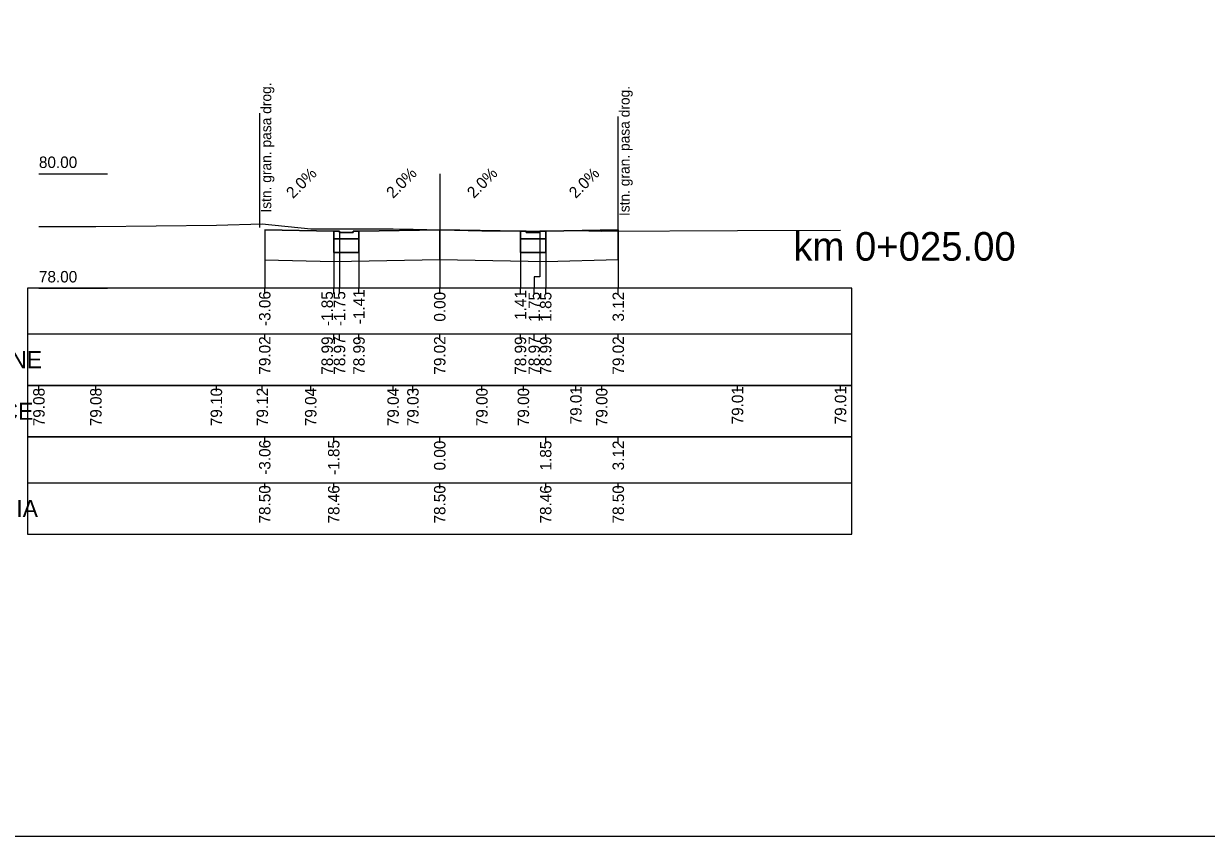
# Model space of a CAD drawing. Extents: x 7492871 to 7493499, y 5802964 to 5802992.
# Drawn here: x 7493052.48 to 7493073.13, y 5802963.88 to 5802978.08 of the extents above; entities that cross this region are included whole.
import ezdxf

# ---------------------------------------------------------------- set-up
doc = ezdxf.new("R2010")
doc.units = 0
for name, color, linetype in [('_wydruk', 7, 'Continuous'), ('opisy_ramki_pop', 7, 'Continuous'), ('pop_comp_kostka', 7, 'Continuous'), ('pop_comp_lawa', 7, 'Continuous'), ('pop_comp_scieralna', 7, 'Continuous'), ('pop_granica_istn', 7, 'Continuous'), ('pop_opis', 7, 'Continuous'), ('pop_os', 7, 'Continuous'), ('pop_pikietaz', 7, 'Continuous'), ('pop_teren', 7, 'Continuous')]:
    doc.layers.add(name, color=color, linetype=linetype)

msp = doc.modelspace()

# ---------------------------------------------------------------- linework, layer by layer
msp.add_lwpolyline([(7493056.687, 5802974.476), (7493057.892, 5802974.452), (7493057.992, 5802974.452), (7493057.993, 5802974.432), (7493058.232, 5802974.432), (7493058.233, 5802974.452), (7493058.333, 5802974.452), (7493059.743, 5802974.48), (7493061.153, 5802974.452), (7493061.253, 5802974.452), (7493061.254, 5802974.432), (7493061.493, 5802974.432), (7493061.494, 5802974.452), (7493061.594, 5802974.452), (7493062.862, 5802974.477)])
at = {"layer": '_wydruk'}
msp.add_lwpolyline([(7492871.369, 5802992.281), (7493499.283, 5802992.281), (7493499.283, 5802963.881), (7492871.369, 5802963.881)], close=True, dxfattribs=at)
at = {"layer": 'opisy_ramki_pop'}
for points in [[(7493056.687, 5802973.956), (7493056.687, 5802973.659), (7493056.687, 5802973.659), (7493056.687, 5802973.459)], [(7493057.892, 5802973.923), (7493057.892, 5802973.659), (7493057.892, 5802973.659), (7493057.892, 5802973.459)], [(7493059.743, 5802973.96), (7493059.743, 5802973.659), (7493059.743, 5802973.659), (7493059.743, 5802973.459)], [(7493061.594, 5802973.923), (7493061.594, 5802973.659), (7493061.594, 5802973.659), (7493061.594, 5802973.459)], [(7493062.862, 5802973.957), (7493062.862, 5802973.659), (7493062.862, 5802973.659), (7493062.862, 5802973.459)]]:
    msp.add_lwpolyline(points, dxfattribs=at)
at = {"layer": 'pop_comp_kostka'}
for p, q in [((7493057.992, 5802974.452), (7493057.892, 5802974.452)), ((7493057.892, 5802974.452), (7493057.892, 5802974.322)), ((7493057.892, 5802974.322), (7493058.333, 5802974.322)), ((7493057.993, 5802974.432), (7493057.992, 5802974.452)), ((7493058.232, 5802974.432), (7493057.993, 5802974.432)), ((7493058.233, 5802974.452), (7493058.232, 5802974.432)), ((7493058.333, 5802974.452), (7493058.233, 5802974.452)), ((7493058.333, 5802974.322), (7493058.333, 5802974.452)), ((7493061.253, 5802974.452), (7493061.153, 5802974.452)), ((7493061.153, 5802974.452), (7493061.153, 5802974.322)), ((7493061.153, 5802974.322), (7493061.594, 5802974.322)), ((7493061.254, 5802974.432), (7493061.253, 5802974.452)), ((7493061.493, 5802974.432), (7493061.254, 5802974.432)), ((7493061.494, 5802974.452), (7493061.493, 5802974.432)), ((7493061.594, 5802974.452), (7493061.494, 5802974.452)), ((7493061.594, 5802974.322), (7493061.594, 5802974.452))]:
    msp.add_line(p, q, dxfattribs=at)
at = {"layer": 'pop_comp_lawa'}
for p, q in [((7493058.333, 5802974.322), (7493057.892, 5802974.322)), ((7493057.892, 5802974.322), (7493057.892, 5802974.081)), ((7493058.333, 5802974.081), (7493058.333, 5802974.322)), ((7493061.594, 5802974.322), (7493061.153, 5802974.322)), ((7493061.153, 5802974.322), (7493061.153, 5802974.081)), ((7493061.594, 5802974.081), (7493061.594, 5802974.322)), ((7493057.892, 5802974.081), (7493058.333, 5802974.081)), ((7493061.153, 5802974.081), (7493061.594, 5802974.081))]:
    msp.add_line(p, q, dxfattribs=at)
at = {"layer": 'pop_comp_scieralna'}
for p, q in [((7493057.892, 5802974.452), (7493056.687, 5802974.476)), ((7493056.687, 5802974.476), (7493056.687, 5802973.956)), ((7493057.892, 5802974.081), (7493057.892, 5802974.452)), ((7493059.743, 5802974.48), (7493058.333, 5802974.452)), ((7493058.333, 5802974.452), (7493058.333, 5802974.081)), ((7493059.743, 5802973.96), (7493059.743, 5802974.48)), ((7493061.153, 5802974.452), (7493059.743, 5802974.48)), ((7493059.743, 5802974.48), (7493059.743, 5802973.96)), ((7493061.153, 5802974.081), (7493061.153, 5802974.452)), ((7493062.862, 5802974.477), (7493061.594, 5802974.452)), ((7493061.594, 5802974.452), (7493061.594, 5802974.081)), ((7493062.862, 5802973.957), (7493062.862, 5802974.477)), ((7493056.687, 5802973.956), (7493057.892, 5802973.923)), ((7493058.333, 5802974.081), (7493057.892, 5802974.081)), ((7493057.892, 5802973.923), (7493059.743, 5802973.96)), ((7493059.743, 5802973.96), (7493061.594, 5802973.923)), ((7493061.594, 5802974.081), (7493061.153, 5802974.081)), ((7493061.594, 5802973.923), (7493062.862, 5802973.957))]:
    msp.add_line(p, q, dxfattribs=at)
at = {"layer": 'pop_granica_istn'}
for p, q in [((7493056.603, 5802975.018), (7493056.603, 5802976.518)), ((7493062.862, 5802974.957), (7493062.862, 5802976.457)), ((7493056.603, 5802974.518), (7493056.603, 5802975.018)), ((7493062.862, 5802974.457), (7493062.862, 5802974.957))]:
    msp.add_line(p, q, dxfattribs=at)
at = {"layer": 'pop_opis'}
for p, q in [((7493052.743, 5802975.459), (7493053.943, 5802975.459)), ((7493052.543, 5802973.459), (7493052.543, 5802971.759)), ((7493052.543, 5802973.459), (7493052.543, 5802971.759)), ((7493052.543, 5802973.459), (7493052.543, 5802971.759)), ((7493052.543, 5802973.459), (7493052.543, 5802971.759)), ((7493052.743, 5802973.459), (7493053.943, 5802973.459)), ((7493056.687, 5802973.359), (7493056.687, 5802973.459)), ((7493057.892, 5802973.359), (7493057.892, 5802973.459)), ((7493057.993, 5802973.359), (7493057.993, 5802973.459)), ((7493058.333, 5802973.359), (7493058.333, 5802973.459)), ((7493059.743, 5802973.359), (7493059.743, 5802973.459)), ((7493061.153, 5802973.359), (7493061.153, 5802973.459)), ((7493061.394, 5802973.359), (7493061.394, 5802973.459)), ((7493061.594, 5802973.359), (7493061.594, 5802973.459)), ((7493062.862, 5802973.359), (7493062.862, 5802973.459)), ((7493052.543, 5802972.659), (7493066.943, 5802972.659)), ((7493052.543, 5802972.659), (7493066.943, 5802972.659)), ((7493052.543, 5802972.659), (7493066.943, 5802972.659)), ((7493052.543, 5802972.659), (7493066.943, 5802972.659)), ((7493056.687, 5802972.559), (7493056.687, 5802972.659)), ((7493057.892, 5802972.559), (7493057.892, 5802972.659)), ((7493057.993, 5802972.559), (7493057.993, 5802972.659)), ((7493058.333, 5802972.559), (7493058.333, 5802972.659)), ((7493059.743, 5802972.559), (7493059.743, 5802972.659)), ((7493061.153, 5802972.559), (7493061.153, 5802972.659)), ((7493061.394, 5802972.559), (7493061.394, 5802972.659)), ((7493061.594, 5802972.559), (7493061.594, 5802972.659)), ((7493062.862, 5802972.559), (7493062.862, 5802972.659)), ((7493052.543, 5802971.759), (7493052.543, 5802970.859)), ((7493052.743, 5802971.659), (7493052.743, 5802971.759)), ((7493053.738, 5802971.659), (7493053.738, 5802971.759)), ((7493055.842, 5802971.659), (7493055.842, 5802971.759)), ((7493056.645, 5802971.659), (7493056.645, 5802971.759)), ((7493057.49, 5802971.659), (7493057.49, 5802971.759)), ((7493058.929, 5802971.659), (7493058.929, 5802971.759)), ((7493059.275, 5802971.659), (7493059.275, 5802971.759)), ((7493060.48, 5802971.659), (7493060.48, 5802971.759)), ((7493061.204, 5802971.659), (7493061.204, 5802971.759)), ((7493062.122, 5802971.659), (7493062.122, 5802971.759)), ((7493062.572, 5802971.659), (7493062.572, 5802971.759)), ((7493064.944, 5802971.659), (7493064.944, 5802971.759)), ((7493066.743, 5802971.659), (7493066.743, 5802971.759)), ((7493052.543, 5802970.859), (7493052.543, 5802969.159)), ((7493056.687, 5802970.759), (7493056.687, 5802970.859)), ((7493057.892, 5802970.759), (7493057.892, 5802970.859)), ((7493059.743, 5802970.759), (7493059.743, 5802970.859)), ((7493061.594, 5802970.759), (7493061.594, 5802970.859)), ((7493062.862, 5802970.759), (7493062.862, 5802970.859)), ((7493052.543, 5802970.059), (7493066.943, 5802970.059)), ((7493056.687, 5802969.959), (7493056.687, 5802970.059)), ((7493057.892, 5802969.959), (7493057.892, 5802970.059)), ((7493059.743, 5802969.959), (7493059.743, 5802970.059)), ((7493061.594, 5802969.959), (7493061.594, 5802970.059)), ((7493062.862, 5802969.959), (7493062.862, 5802970.059))]:
    msp.add_line(p, q, dxfattribs=at)
for points in [[(7493056.687, 5802974.476), (7493056.687, 5802973.659), (7493056.687, 5802973.659), (7493056.687, 5802973.459)], [(7493057.892, 5802974.452), (7493057.892, 5802973.659), (7493057.892, 5802973.659), (7493057.892, 5802973.459)], [(7493057.993, 5802974.432), (7493057.993, 5802973.659), (7493057.993, 5802973.659), (7493057.993, 5802973.459)], [(7493058.333, 5802974.452), (7493058.333, 5802973.659), (7493058.333, 5802973.659), (7493058.333, 5802973.459)], [(7493059.743, 5802974.48), (7493059.743, 5802973.659), (7493059.743, 5802973.659), (7493059.743, 5802973.459)], [(7493061.153, 5802974.452), (7493061.153, 5802973.659), (7493061.153, 5802973.659), (7493061.153, 5802973.459)], [(7493061.493, 5802974.432), (7493061.493, 5802973.659), (7493061.394, 5802973.659), (7493061.394, 5802973.459)], [(7493061.594, 5802974.452), (7493061.594, 5802973.659), (7493061.594, 5802973.659), (7493061.594, 5802973.459)], [(7493062.862, 5802974.477), (7493062.862, 5802973.659), (7493062.862, 5802973.659), (7493062.862, 5802973.459)]]:
    msp.add_lwpolyline(points, dxfattribs=at)
for points in [[(7493052.543, 5802973.459), (7493052.543, 5802971.759), (7493066.943, 5802971.759), (7493066.943, 5802973.459)], [(7493052.543, 5802973.459), (7493052.543, 5802971.759), (7493066.943, 5802971.759), (7493066.943, 5802973.459)], [(7493052.543, 5802973.459), (7493052.543, 5802971.759), (7493066.943, 5802971.759), (7493066.943, 5802973.459)], [(7493052.543, 5802973.459), (7493052.543, 5802971.759), (7493066.943, 5802971.759), (7493066.943, 5802973.459)], [(7493052.543, 5802971.759), (7493052.543, 5802970.859), (7493066.943, 5802970.859), (7493066.943, 5802971.759)], [(7493052.543, 5802970.859), (7493052.543, 5802969.159), (7493066.943, 5802969.159), (7493066.943, 5802970.859)]]:
    msp.add_lwpolyline(points, close=True, dxfattribs=at)
at = {"layer": 'pop_os'}
msp.add_line((7493059.743, 5802975.459), (7493059.743, 5802973.459), dxfattribs=at)
at = {"layer": 'pop_teren'}
msp.add_lwpolyline([(7493052.743, 5802974.538), (7493053.738, 5802974.538), (7493055.842, 5802974.562), (7493056.645, 5802974.582), (7493057.49, 5802974.498), (7493058.929, 5802974.495), (7493059.275, 5802974.492), (7493059.281, 5802974.492), (7493060.48, 5802974.462), (7493061.204, 5802974.455), (7493062.122, 5802974.467), (7493062.572, 5802974.455), (7493064.944, 5802974.465), (7493066.743, 5802974.47)], dxfattribs=at)

# ---------------------------------------------------------------- texts
at = {"layer": 'pop_granica_istn'}
for p in [(7493056.801, 5802974.779), (7493063.06, 5802974.718)]:
    msp.add_text('Istn. gran. pasa drog.', height=0.18, rotation=90, dxfattribs=at).set_placement(p)
at = {"layer": 'pop_opis'}
for s, height, p in [('80.00', 0.2, (7493052.743, 5802975.559)), ('78.00', 0.2, (7493052.743, 5802973.559)), ('RZĘDNE PROJEKTOWANE', 0.3, (7493047.671, 5802972.059)), ('RZĘDNE PROJEKTOWANE', 0.3, (7493047.671, 5802972.059)), ('RZĘDNE PROJEKTOWANE', 0.3, (7493047.671, 5802972.059)), ('RZĘDNE PROJEKTOWANE', 0.3, (7493047.671, 5802972.059)), ('RZĘDNE ISTNIEJĄCE', 0.3, (7493048.567, 5802971.159)), ('RZĘDNE KORYTOWANIA', 0.3, (7493047.957, 5802969.459))]:
    msp.add_text(s, height=height, dxfattribs=at).set_placement(p)
for s, rotation, p in [('2.0%', 45, (7493057.181, 5802975.013)), ('2.0%', 45, (7493058.929, 5802975.016)), ('2.0%', 45, (7493060.339, 5802975.016)), ('2.0%', 45, (7493062.119, 5802975.014)), ('-3.06', 90, (7493056.787, 5802972.798)), ('-1.85', 90, (7493057.878, 5802972.796)), ('-1.75', 90, (7493058.093, 5802972.796)), ('-1.41', 90, (7493058.433, 5802972.829)), ('0.00', 90, (7493059.843, 5802972.874)), ('1.41', 90, (7493061.253, 5802972.905)), ('1.75', 90, (7493061.494, 5802972.873)), ('1.85', 90, (7493061.694, 5802972.873)), ('3.12', 90, (7493062.962, 5802972.875)), ('79.02', 90, (7493056.787, 5802971.948)), ('78.99', 90, (7493057.878, 5802971.946)), ('78.97', 90, (7493058.093, 5802971.947)), ('78.99', 90, (7493058.433, 5802971.946)), ('79.02', 90, (7493059.843, 5802971.948)), ('78.99', 90, (7493061.253, 5802971.946)), ('78.97', 90, (7493061.494, 5802971.947)), ('78.99', 90, (7493061.694, 5802971.946)), ('79.02', 90, (7493062.962, 5802971.948)), ('79.08', 90, (7493052.843, 5802971.046)), ('79.08', 90, (7493053.838, 5802971.046)), ('79.10', 90, (7493055.942, 5802971.047)), ('79.12', 90, (7493056.745, 5802971.048)), ('79.04', 90, (7493057.59, 5802971.047)), ('79.04', 90, (7493059.029, 5802971.047)), ('79.03', 90, (7493059.375, 5802971.047)), ('79.00', 90, (7493060.58, 5802971.047)), ('79.00', 90, (7493061.304, 5802971.047)), ('79.01', 90, (7493062.222, 5802971.078)), ('79.00', 90, (7493062.672, 5802971.047)), ('79.01', 90, (7493065.044, 5802971.078)), ('79.01', 90, (7493066.843, 5802971.078)), ('-3.06', 90, (7493056.787, 5802970.198)), ('-1.85', 90, (7493057.992, 5802970.196)), ('0.00', 90, (7493059.843, 5802970.274)), ('1.85', 90, (7493061.694, 5802970.273)), ('3.12', 90, (7493062.962, 5802970.275)), ('78.50', 90, (7493056.787, 5802969.347)), ('78.46', 90, (7493057.992, 5802969.347)), ('78.50', 90, (7493059.843, 5802969.347)), ('78.46', 90, (7493061.694, 5802969.347)), ('78.50', 90, (7493062.962, 5802969.347))]:
    msp.add_text(s, height=0.2, rotation=rotation, dxfattribs=at).set_placement(p)
at = {"layer": 'pop_pikietaz'}
msp.add_text('km 0+025.00', height=0.5, dxfattribs=at).set_placement((7493065.919, 5802973.939))

doc.saveas('drawing.dxf')
